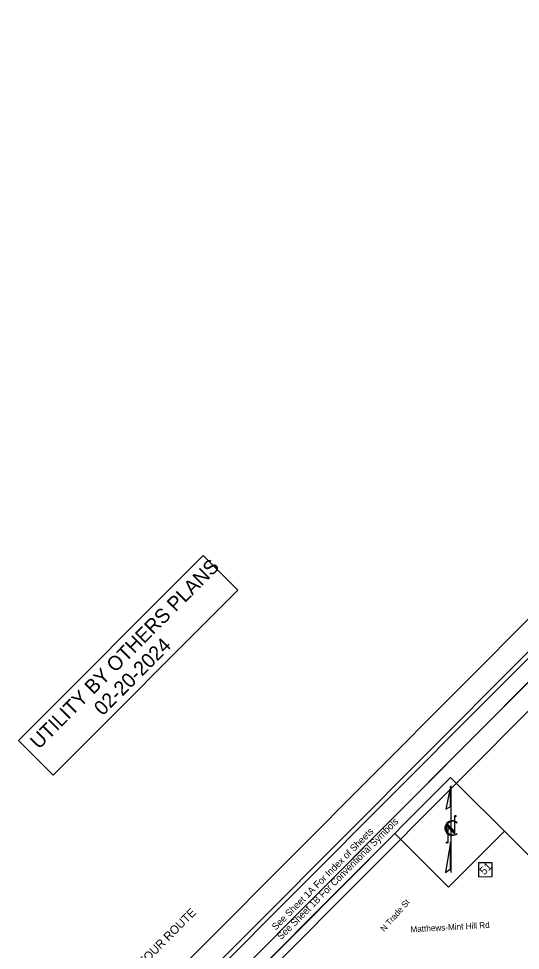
# Model space of a CAD drawing. Extents: x 1484850 to 1495577, y 495475 to 506245.
# Drawn here: x 1484850 to 1486494, y 498431 to 501486 of the extents above; entities that cross this region are included whole.
import ezdxf

# ---------------------------------------------------------------- set-up
doc = ezdxf.new("R2010")
doc.units = 0
for name, color, linetype in [('Cell Prop Down Guy _B', 7, 'Continuous'), ('Default', 7, 'Continuous'), ('Exist Utilities TV Pedestal CELL', 7, 'Continuous'), ('Exist Utilities Water Fire Hydrant CELL', 7, 'Continuous'), ('Exist Utilities Water Meter CELL', 7, 'Continuous'), ('Exist Utilities Water UG Line SUE LOS C', 7, 'Continuous'), ('P Pole (Pow Co) CELL', 7, 'Continuous'), ('Prop Conduit _B', 7, 'Continuous'), ('Prop Guy Wire', 7, 'Continuous'), ('Prop UG Pow Cables', 7, 'Continuous')]:
    doc.layers.add(name, color=color, linetype=linetype)

msp = doc.modelspace()

# ---------------------------------------------------------------- linework, layer by layer
at = {"layer": 'Cell Prop Down Guy _B'}
msp.add_line((1485019.4, 497803.9), (1488584.2, 501383.6), dxfattribs=at)
msp.add_lwpolyline([(1485019.4, 497803.9), (1488584.2, 501383.6), (1490922.5, 499055), (1487357.7, 495475.3)], close=True, dxfattribs=at)
at = {"layer": 'Exist Utilities TV Pedestal CELL'}
for p, q in [((1486402, 498718.1), (1486356.9, 498718.5)), ((1486356.9, 498718.5), (1486357, 498672.9)), ((1486402.1, 498673.5), (1486402, 498718.1)), ((1486357, 498672.9), (1486402.1, 498673.5))]:
    msp.add_line(p, q, dxfattribs=at)
at = {"layer": 'Exist Utilities Water Fire Hydrant CELL'}
for p, q in [((1486267.6, 498686.4), (1486267.8, 498970.9)), ((1486278.4, 498871.9), (1486278.4, 498813.5)), ((1486256.7, 498844.4), (1486256.6, 498785)), ((1486278.4, 498822.6), (1486256.7, 498844.4)), ((1486278.4, 498820.5), (1486256.7, 498842.2)), ((1486256.7, 498842.2), (1486256.7, 498836.9)), ((1486278.4, 498815.1), (1486256.7, 498836.9)), ((1486256.7, 498836.9), (1486278.4, 498815.1)), ((1486278.4, 498813.5), (1486256.7, 498835.3)), ((1486286.5, 498850.1), (1486286.8, 498849.9)), ((1486278.4, 498815.1), (1486278.4, 498820.5))]:
    msp.add_line(p, q, dxfattribs=at)
for points in [[(1486265.8, 498968.4), (1486249.5, 498894.5), (1486265.8, 498902.8)], [(1486265.3, 498786.7), (1486249.2, 498686.5), (1486265.3, 498699.1)]]:
    msp.add_lwpolyline(points, close=True, dxfattribs=at)
for centre in [(1486280.8, 498871.8), (1486254.3, 498785)]:
    msp.add_circle(centre, 2.32, dxfattribs=at)
for centre, radius, start, end in [((1486270.7, 498832.2), 23.9, 47.7961, 312.3501), ((1486273, 498832.2), 22.4, 53.0511, 308.5848)]:
    msp.add_arc(centre, radius, start, end, dxfattribs=at)
at = {"layer": 'Exist Utilities Water UG Line SUE LOS C'}
for points in [[(1486441.9, 498821.9), (1486895.2, 498370.5), (1486217.1, 497689.6), (1485587.2, 498316.9), (1486082.4, 498814.2), (1486259, 498638.3)], [(1486441.9, 498821.9), (1486895.4, 498370.4), (1486217.3, 497689.5), (1485587.4, 498316.8), (1486082.5, 498814.1), (1486259, 498638.3)]]:
    msp.add_lwpolyline(points, close=True, dxfattribs=at)
at = {"layer": 'P Pole (Pow Co) CELL'}
msp.add_lwpolyline([(1488481.3, 501486.1), (1484916.4, 497906.4), (1487254.7, 495577.9), (1490819.6, 499157.6)], close=True, dxfattribs=at)
at = {"layer": 'Prop Conduit _B'}
msp.add_lwpolyline([(1484963.5, 499005.9), (1484849.9, 499119.1), (1485454.3, 499726), (1485567.9, 499612.8)], close=True, dxfattribs=at)
at = {"layer": 'Prop Guy Wire'}
msp.add_lwpolyline([(1487337.5, 495550.5), (1490865.3, 499093), (1488622.4, 501326.5), (1485094.6, 497784)], close=True, dxfattribs=at)
at = {"layer": 'Prop UG Pow Cables'}
for points in [[(1488477.3, 501375.9), (1485344.2, 498229.8)], [(1488477.3, 501354.6), (1485471.3, 498336.1)]]:
    msp.add_lwpolyline(points, dxfattribs=at)
for points in [[(1486895.2, 498370.5), (1486217.1, 497689.6), (1485587.2, 498316.9), (1486265.2, 498997.8)], [(1485587.2, 498316.9), (1486082.4, 498814.2), (1486259, 498638.3), (1486441.9, 498821.9), (1486895, 498370.6), (1486217, 497689.7)]]:
    msp.add_lwpolyline(points, close=True, dxfattribs=at)

# ---------------------------------------------------------------- texts
at = {"layer": 'Default'}
for s, rotation, p in [('N Trade St', 48.7859, (1486048.3, 498491)), ('Matthews-Mint Hill Rd', 3.2578, (1486134.5, 498490.3))]:
    msp.add_text(s, height=20, rotation=rotation, dxfattribs=at).set_placement(p)
at = {"layer": 'Exist Utilities TV Pedestal CELL'}
msp.add_text('51', height=26.25, rotation=45.1186, dxfattribs=at).set_placement((1486376.1, 498676.6))
at = {"layer": 'Exist Utilities Water Meter CELL'}
msp.add_text('DETOUR ROUTE', height=28, rotation=45.1191, dxfattribs=at).set_placement((1485222.5, 498340.7))
at = {"layer": 'Prop Conduit _B'}
for s, height, p in [('UTILITY BY OTHERS PLANS', 47.263, (1484916, 499088.6)), ('02-20-2024', 47.26, (1485125.3, 499198.3))]:
    msp.add_text(s, height=height, rotation=45.1191, dxfattribs=at).set_placement(p)
at = {"layer": 'Prop UG Pow Cables'}
for s, p in [('See Sheet 1B For Conventional Symbols', (1485710.4, 498464.6)), ('See Sheet 1A For Index of Sheets', (1485692.8, 498496))]:
    msp.add_text(s, height=22.5, rotation=45.1191, dxfattribs=at).set_placement(p)

doc.saveas('drawing.dxf')
